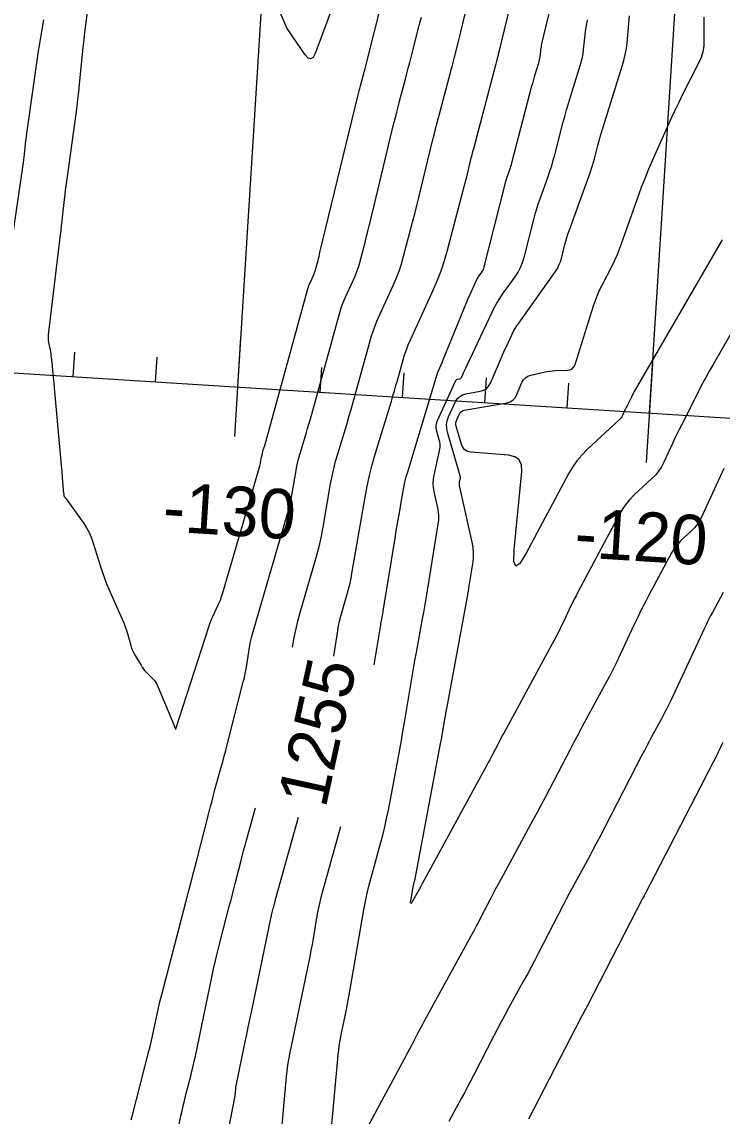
# Model space of a CAD drawing. Extents: x 658976 to 668726, y 639543 to 647196.
# Drawn here: x 661695.1 to 661779.9, y 641758.1 to 641890.7 of the extents above; entities that cross this region are included whole.
import ezdxf

# ---------------------------------------------------------------- set-up
doc = ezdxf.new("R2010")
doc.units = 0
for name, color, linetype in [('Ex_Contour Labels', 7, 'Continuous'), ('Ex_Major Contours', 7, 'Continuous'), ('Ex_Minor Contours', 7, 'Continuous'), ('R_Axis', 7, 'Continuous'), ('R_Axis Annot', 7, 'Continuous'), ('R_Grid', 7, 'Continuous')]:
    doc.layers.add(name, color=color, linetype=linetype)

msp = doc.modelspace()

# ---------------------------------------------------------------- linework, layer by layer
at = {"layer": 'Ex_Major Contours'}
for points in [[(661732.85, 641813.83), (661733.34, 641816.91), (661733.44, 641817.5), (661733.56, 641818.08), (661733.7, 641818.66), (661733.86, 641819.23), (661734.53, 641821.51), (661734.68, 641822.09), (661734.83, 641822.66), (661734.95, 641823.24), (661735.06, 641823.83), (661736.66, 641833.08), (661736.91, 641834.4), (661737.19, 641835.7), (661737.52, 641837), (661737.89, 641838.28), (661739.84, 641844.73), (661740.03, 641845.35), (661740.21, 641845.98), (661740.39, 641846.6), (661740.56, 641847.22), (661741.25, 641849.72), (661741.44, 641850.34), (661741.65, 641850.95), (661741.88, 641851.56), (661742.14, 641852.15), (661744.87, 641858.1), (661745.39, 641859.3), (661745.86, 641860.51), (661746.27, 641861.75), (661746.63, 641863), (661748.66, 641870.73), (661748.76, 641871.12), (661748.86, 641871.5), (661748.96, 641871.88), (661749.05, 641872.27), (661749.42, 641873.8), (661749.51, 641874.19), (661749.61, 641874.57), (661749.71, 641874.95), (661749.81, 641875.33), (661752.5, 641885.47), (661752.53, 641885.6), (661752.56, 641885.73), (661752.6, 641885.86), (661752.63, 641885.99), (661752.77, 641886.52), (661752.8, 641886.65), (661752.83, 641886.78), (661752.86, 641886.91), (661752.9, 641887.04), (661757.15, 641904.55)], [(661779.98, 641803.37), (661779.9, 641803.2), (661779.83, 641803.03), (661779.52, 641802.34), (661779.44, 641802.17), (661779.36, 641802), (661779.28, 641801.84), (661779.19, 641801.67), (661778.48, 641800.3), (661778.34, 641800.01), (661778.19, 641799.73), (661778.04, 641799.45), (661777.89, 641799.16), (661770.58, 641785.02), (661770.55, 641784.96), (661770.52, 641784.91), (661770.49, 641784.85), (661770.47, 641784.8), (661770.35, 641784.58), (661770.32, 641784.53), (661770.29, 641784.47), (661770.26, 641784.42), (661770.23, 641784.36), (661763.6, 641771.5), (661763.53, 641771.37), (661763.46, 641771.24), (661763.39, 641771.1), (661763.31, 641770.97), (661763.02, 641770.44), (661762.95, 641770.31), (661762.88, 641770.18), (661762.81, 641770.04), (661762.74, 641769.91), (661756.44, 641757.73)], [(661717.06, 641740.79), (661720.89, 641760.56), (661720.9, 641760.63), (661720.91, 641760.7), (661720.92, 641760.77), (661720.93, 641760.84), (661720.99, 641761.57), (661721, 641761.62), (661721.01, 641761.67), (661721.02, 641761.73), (661721.02, 641761.78), (661722.12, 641767.08), (661722.31, 641767.98), (661722.5, 641768.88), (661722.68, 641769.78), (661722.87, 641770.68), (661725.23, 641782.04), (661725.26, 641782.18), (661725.29, 641782.32), (661725.32, 641782.46), (661725.36, 641782.59), (661725.53, 641783.24), (661725.55, 641783.33), (661725.58, 641783.42), (661725.6, 641783.51), (661725.62, 641783.6), (661725.72, 641783.97), (661725.74, 641784.06), (661725.76, 641784.15), (661725.79, 641784.24), (661725.81, 641784.33), (661728.57, 641794.3)]]:
    msp.add_lwpolyline(points, dxfattribs=at)
at = {"layer": 'Ex_Minor Contours'}
for points in [[(661727.84, 641814.93), (661728.01, 641815.89), (661728.24, 641816.98), (661728.5, 641818.06), (661728.79, 641819.13), (661730.57, 641825.22), (661730.88, 641826.33), (661731.16, 641827.45), (661731.4, 641828.58), (661731.61, 641829.71), (661732.47, 641834.7), (661732.65, 641835.62), (661732.85, 641836.53), (661733.08, 641837.43), (661733.33, 641838.33), (661734.42, 641841.9), (661734.68, 641842.8), (661734.95, 641843.69), (661735.2, 641844.59), (661735.45, 641845.49), (661737.17, 641851.74), (661737.44, 641852.65), (661737.75, 641853.54), (661738.09, 641854.42), (661738.47, 641855.28), (661740.04, 641858.72), (661740.42, 641859.59), (661740.76, 641860.47), (661741.06, 641861.36), (661741.32, 641862.27), (661742.41, 641866.42), (661742.67, 641867.42), (661742.92, 641868.41), (661743.17, 641869.41), (661743.42, 641870.41), (661744.54, 641875.07), (661744.79, 641876.11), (661745.05, 641877.14), (661745.32, 641878.18), (661745.59, 641879.21), (661746.96, 641884.38), (661747.09, 641884.89), (661747.23, 641885.4), (661747.36, 641885.91), (661747.49, 641886.41), (661748.01, 641888.45), (661748.14, 641888.95), (661748.26, 641889.46), (661748.39, 641889.97), (661748.51, 641890.48), (661751.31, 641901.98)], [(661737.74, 641812.76), (661738.51, 641817.38), (661738.54, 641817.56), (661738.57, 641817.74), (661738.6, 641817.91), (661738.63, 641818.09), (661738.76, 641818.79), (661738.79, 641818.97), (661738.83, 641819.15), (661738.86, 641819.32), (661738.88, 641819.5), (661740.32, 641828.37), (661740.43, 641829.03), (661740.54, 641829.68), (661740.65, 641830.33), (661740.76, 641830.99), (661741.21, 641833.59), (661741.33, 641834.24), (661741.47, 641834.89), (661741.64, 641835.53), (661741.82, 641836.16), (661745.47, 641848.23), (661745.48, 641848.24), (661745.48, 641848.26), (661745.49, 641848.27), (661745.49, 641848.29), (661745.51, 641848.35), (661745.51, 641848.36), (661745.52, 641848.38), (661745.52, 641848.39), (661745.53, 641848.41), (661745.86, 641849.12), (661745.92, 641849.25), (661745.97, 641849.37), (661746.02, 641849.5), (661746.08, 641849.63), (661748.99, 641856.76), (661749.11, 641857.06), (661749.24, 641857.36), (661749.37, 641857.65), (661749.51, 641857.94), (661750.21, 641859.45), (661750.28, 641859.57), (661750.34, 641859.69), (661750.41, 641859.8), (661750.49, 641859.91), (661750.8, 641860.36), (661750.88, 641860.47), (661750.94, 641860.59), (661750.99, 641860.71), (661751.03, 641860.84), (661753.65, 641871.15), (661753.71, 641871.36), (661753.77, 641871.56), (661753.83, 641871.77), (661753.9, 641871.97), (661754.2, 641872.79), (661754.27, 641872.99), (661754.33, 641873.2), (661754.4, 641873.4), (661754.45, 641873.61), (661756.87, 641882.91), (661756.96, 641883.22), (661757.05, 641883.54), (661757.14, 641883.85), (661757.23, 641884.17), (661757.71, 641885.71), (661757.76, 641885.88), (661757.8, 641886.06), (661757.84, 641886.23), (661757.86, 641886.41), (661757.93, 641887.13), (661757.95, 641887.31), (661757.97, 641887.49), (661758.01, 641887.66), (661758.04, 641887.84), (661761.38, 641901.77)], [(661704.08, 641900.36), (661702.77, 641890.3), (661702.66, 641889.4), (661702.56, 641888.5), (661702.46, 641887.61), (661702.37, 641886.71), (661702.01, 641883.11), (661701.92, 641882.21), (661701.82, 641881.31), (661701.71, 641880.42), (661701.59, 641879.52), (661700.46, 641871.32), (661700.39, 641870.79), (661700.32, 641870.25), (661700.26, 641869.71), (661700.2, 641869.17), (661699.96, 641867.02), (661699.9, 641866.48), (661699.84, 641865.94), (661699.77, 641865.4), (661699.71, 641864.86), (661698.26, 641852.76), (661698.25, 641852.52), (661698.24, 641852.3), (661698.26, 641852.07), (661698.3, 641851.84), (661698.47, 641850.92), (661698.51, 641850.7), (661698.55, 641850.47), (661698.58, 641850.24), (661698.61, 641850.01), (661698.72, 641849.06), (661698.75, 641848.83), (661698.77, 641848.6), (661698.79, 641848.36), (661698.82, 641848.13), (661699.87, 641836.49), (661699.89, 641836.23), (661699.91, 641835.97), (661699.94, 641835.71), (661699.96, 641835.44), (661700.06, 641834.02), (661700.07, 641833.94), (661700.08, 641833.86), (661700.08, 641833.79), (661700.09, 641833.71), (661700.13, 641833.34), (661700.14, 641833.3), (661700.15, 641833.25), (661700.17, 641833.21), (661700.2, 641833.18), (661700.3, 641833.03), (661700.33, 641832.99), (661700.36, 641832.96), (661700.38, 641832.92), (661700.41, 641832.88), (661702.55, 641829.88), (661702.9, 641829.35), (661703.2, 641828.81), (661703.45, 641828.24), (661703.66, 641827.65), (661704.59, 641824.67), (661704.82, 641823.97), (661705.06, 641823.28), (661705.33, 641822.6), (661705.61, 641821.93), (661707.36, 641817.93), (661707.5, 641817.6), (661707.63, 641817.26), (661707.74, 641816.92), (661707.85, 641816.57), (661708.26, 641815.11), (661708.36, 641814.8), (661708.48, 641814.5), (661708.62, 641814.2), (661708.77, 641813.92), (661709.5, 641812.71), (661709.64, 641812.48), (661709.81, 641812.26), (661709.98, 641812.04), (661710.17, 641811.84), (661710.95, 641811.06), (661711.13, 641810.86), (661711.29, 641810.64), (661711.43, 641810.41), (661711.55, 641810.16), (661713.5, 641805.41), (661713.53, 641805.36), (661713.55, 641805.31), (661713.56, 641805.26), (661713.58, 641805.21), (661713.66, 641805), (661713.68, 641804.96), (661713.69, 641804.95), (661713.71, 641804.96), (661713.73, 641805), (661717.7, 641817.37), (661717.82, 641817.72), (661717.94, 641818.06), (661718.08, 641818.39), (661718.23, 641818.72), (661718.86, 641820.04), (661719.01, 641820.37), (661719.15, 641820.7), (661719.27, 641821.04), (661719.38, 641821.39), (661723.86, 641836.71), (661723.9, 641836.85), (661723.93, 641837), (661723.97, 641837.15), (661723.99, 641837.3), (661724.11, 641837.95), (661724.13, 641838.07), (661724.16, 641838.19), (661724.19, 641838.31), (661724.22, 641838.42), (661724.36, 641838.89), (661724.4, 641839.01), (661724.43, 641839.13), (661724.46, 641839.24), (661724.5, 641839.36), (661729.72, 641858.32), (661729.78, 641858.53), (661729.85, 641858.74), (661729.93, 641858.95), (661730.02, 641859.15), (661730.39, 641859.96), (661730.48, 641860.16), (661730.56, 641860.37), (661730.63, 641860.58), (661730.69, 641860.79), (661730.95, 641861.77), (661731.01, 641862), (661731.07, 641862.24), (661731.13, 641862.47), (661731.18, 641862.71), (661735.77, 641881.69), (661735.84, 641881.99), (661735.92, 641882.3), (661736, 641882.6), (661736.08, 641882.91), (661736.4, 641884.12), (661736.48, 641884.43), (661736.56, 641884.73), (661736.64, 641885.04), (661736.72, 641885.34), (661738.85, 641893.72)], [(661734.54, 641897.51), (661730.59, 641886.82), (661730.34, 641886.35), (661730.07, 641886.18), (661729.75, 641886.28), (661729.4, 641886.67), (661727.2, 641889.85), (661727.2, 641889.86), (661725.47, 641893.87)], [(661708.31, 641757.63), (661708.46, 641758.22), (661710.46, 641765.95), (661710.6, 641766.51), (661710.74, 641767.07), (661710.86, 641767.63), (661710.98, 641768.19), (661711.45, 641770.44), (661711.57, 641771), (661711.7, 641771.56), (661711.83, 641772.12), (661711.98, 641772.68), (661714.94, 641784.03), (661715.26, 641785.26), (661715.58, 641786.48), (661715.9, 641787.71), (661716.21, 641788.94), (661717.74, 641794.94), (661717.92, 641795.62), (661718.1, 641796.3), (661718.28, 641796.98), (661718.46, 641797.65), (661719.21, 641800.36), (661719.4, 641801.03), (661719.58, 641801.71), (661719.76, 641802.39), (661719.94, 641803.07), (661721.89, 641810.7), (661722.02, 641811.21), (661722.13, 641811.73), (661722.23, 641812.25), (661722.32, 641812.77), (661722.65, 641814.86), (661722.74, 641815.38), (661722.84, 641815.89), (661722.97, 641816.41), (661723.11, 641816.91), (661727.22, 641830.96), (661727.39, 641831.59), (661727.55, 641832.23), (661727.68, 641832.86), (661727.8, 641833.51), (661728.29, 641836.33), (661728.39, 641836.85), (661728.5, 641837.36), (661728.63, 641837.87), (661728.78, 641838.38), (661729.39, 641840.4), (661729.54, 641840.9), (661729.69, 641841.41), (661729.83, 641841.92), (661729.98, 641842.43), (661733.45, 641855.03), (661733.61, 641855.59), (661733.8, 641856.14), (661734.01, 641856.68), (661734.24, 641857.22), (661735.22, 641859.34), (661735.45, 641859.87), (661735.66, 641860.42), (661735.84, 641860.97), (661736, 641861.53), (661736.68, 641864.09), (661736.84, 641864.71), (661737, 641865.33), (661737.15, 641865.94), (661737.3, 641866.56), (661740.15, 641878.38), (661740.32, 641879.05), (661740.49, 641879.72), (661740.66, 641880.39), (661740.83, 641881.06), (661741.54, 641883.73), (661741.72, 641884.4), (661741.89, 641885.07), (661742.07, 641885.74), (661742.24, 641886.4), (661743.25, 641890.38), (661743.47, 641891.26)], [(661784.9, 641859.68), (661778.81, 641849.17), (661778.34, 641848.34), (661777.88, 641847.5), (661777.43, 641846.66), (661777, 641845.81), (661774.98, 641841.82), (661774.7, 641841.27), (661774.43, 641840.71), (661774.16, 641840.14), (661773.89, 641839.58), (661772.84, 641837.31), (661772.55, 641836.76), (661772.21, 641836.25), (661771.83, 641835.77), (661771.4, 641835.33), (661769.22, 641833.31), (661768.73, 641832.81), (661768.29, 641832.28), (661767.89, 641831.72), (661767.53, 641831.11), (661762.44, 641821.58), (661762.21, 641821.15), (661761.98, 641820.71), (661761.77, 641820.27), (661761.56, 641819.83), (661760.72, 641818.05), (661760.51, 641817.6), (661760.3, 641817.16), (661760.07, 641816.72), (661759.84, 641816.29), (661753.46, 641804.51), (661753.28, 641804.19), (661753.11, 641803.86), (661752.94, 641803.54), (661752.77, 641803.21), (661752.1, 641801.91), (661751.93, 641801.59), (661751.76, 641801.26), (661751.58, 641800.94), (661751.41, 641800.62), (661743.6, 641786.3), (661743.58, 641786.26), (661743.56, 641786.23), (661743.54, 641786.19), (661743.52, 641786.15), (661743.44, 641786), (661743.42, 641785.97), (661743.4, 641785.93), (661743.38, 641785.89), (661743.36, 641785.85), (661742.41, 641784.12), (661742.27, 641783.9), (661742.19, 641783.84), (661742.17, 641783.94), (661742.2, 641784.19), (661742.52, 641786.06), (661742.53, 641786.13), (661742.55, 641786.19), (661742.56, 641786.26), (661742.58, 641786.32), (661742.65, 641786.58), (661742.67, 641786.65), (661742.68, 641786.71), (661742.7, 641786.78), (661742.71, 641786.85), (661745.8, 641803.18), (661745.87, 641803.56), (661745.94, 641803.93), (661746.01, 641804.3), (661746.07, 641804.68), (661746.32, 641806.18), (661746.38, 641806.55), (661746.44, 641806.93), (661746.51, 641807.3), (661746.58, 641807.68), (661748.82, 641819.71), (661748.94, 641820.37), (661749.06, 641821.03), (661749.17, 641821.69), (661749.28, 641822.35), (661749.71, 641824.99), (661749.78, 641825.65), (661749.8, 641826.31), (661749.74, 641826.97), (661749.63, 641827.62), (661748.11, 641834.5), (661748.09, 641834.6), (661748.08, 641834.69), (661748.09, 641834.79), (661748.1, 641834.89), (661748.19, 641835.28), (661748.2, 641835.38), (661748.2, 641835.48), (661748.19, 641835.57), (661748.17, 641835.67), (661746.64, 641840.98), (661746.54, 641841.44), (661746.53, 641841.9), (661746.61, 641842.35), (661746.77, 641842.8), (661747.62, 641844.66), (661747.84, 641845.02), (661748.12, 641845.3), (661748.46, 641845.5), (661748.86, 641845.61), (661750.61, 641845.92), (661751.01, 641846.03), (661751.35, 641846.23), (661751.62, 641846.52), (661751.83, 641846.88), (661753.17, 641850), (661753.32, 641850.35), (661753.48, 641850.71), (661753.64, 641851.06), (661753.81, 641851.42), (661754.47, 641852.83), (661754.65, 641853.18), (661754.84, 641853.51), (661755.04, 641853.85), (661755.26, 641854.17), (661759.71, 641860.43), (661759.95, 641860.8), (661760.14, 641861.18), (661760.31, 641861.58), (661760.43, 641861.99), (661760.86, 641863.69), (661760.98, 641864.11), (661761.1, 641864.53), (661761.23, 641864.95), (661761.38, 641865.36), (661763.95, 641872.5), (661764.09, 641872.89), (661764.21, 641873.28), (661764.33, 641873.68), (661764.44, 641874.08), (661764.86, 641875.68), (661764.96, 641876.08), (661765.07, 641876.48), (661765.19, 641876.87), (661765.31, 641877.27), (661767.82, 641885.29), (661768.02, 641886), (661768.18, 641886.71), (661768.31, 641887.43), (661768.4, 641888.15), (661768.71, 641891.39)], [(661779.91, 641864.26), (661769.39, 641846.08), (661769.27, 641845.87), (661769.15, 641845.65), (661769.03, 641845.43), (661768.92, 641845.21), (661768.39, 641844.16), (661768.32, 641844.01), (661768.24, 641843.87), (661768.17, 641843.72), (661768.1, 641843.57), (661767.83, 641842.98), (661767.75, 641842.83), (661767.67, 641842.7), (661767.56, 641842.57), (661767.45, 641842.46), (661763.56, 641838.84), (661762.9, 641838.18), (661762.3, 641837.47), (661761.77, 641836.71), (661761.29, 641835.9), (661756.15, 641826.29), (661755.39, 641825.06), (661754.9, 641824.73), (661754.68, 641825.28), (661754.73, 641826.72), (661755.64, 641836.2), (661755.61, 641837), (661755.32, 641837.6), (661754.79, 641837.98), (661754.01, 641838.16), (661749.47, 641838.54), (661749.07, 641838.63), (661748.74, 641838.81), (661748.49, 641839.1), (661748.33, 641839.48), (661747.69, 641841.67), (661747.65, 641841.87), (661747.65, 641842.06), (661747.68, 641842.25), (661747.75, 641842.44), (661748.09, 641843.18), (661748.19, 641843.35), (661748.32, 641843.48), (661748.48, 641843.57), (661748.67, 641843.63), (661753.86, 641844.53), (661754.23, 641844.64), (661754.55, 641844.83), (661754.8, 641845.09), (661754.99, 641845.43), (661755.66, 641846.97), (661755.84, 641847.3), (661756.08, 641847.56), (661756.38, 641847.75), (661756.73, 641847.87), (661758.32, 641848.24), (661758.67, 641848.32), (661759.02, 641848.37), (661759.37, 641848.41), (661759.73, 641848.43), (661761.16, 641848.47), (661761.48, 641848.52), (661761.75, 641848.65), (661761.95, 641848.87), (661762.09, 641849.17), (661764.33, 641856.28), (661764.55, 641856.92), (661764.8, 641857.55), (661765.07, 641858.17), (661765.36, 641858.78), (661766.61, 641861.19), (661766.91, 641861.8), (661767.19, 641862.42), (661767.44, 641863.04), (661767.68, 641863.68), (661769.81, 641869.7), (661770.2, 641870.76), (661770.61, 641871.81), (661771.04, 641872.85), (661771.49, 641873.89), (661773.46, 641878.3), (661773.86, 641879.19), (661774.27, 641880.07), (661774.69, 641880.94), (661775.13, 641881.82), (661777.12, 641885.77), (661777.4, 641886.41), (661777.6, 641887.07), (661777.72, 641887.75), (661777.75, 641888.44), (661777.75, 641891.26)], [(661697.68, 641890.92), (661697.35, 641889.02), (661697.27, 641888.55), (661697.19, 641888.07), (661697.12, 641887.6), (661697.05, 641887.12), (661695.62, 641877.16), (661695.57, 641876.84), (661695.53, 641876.52), (661695.49, 641876.21), (661695.46, 641875.89), (661695.33, 641874.61), (661695.3, 641874.29), (661695.26, 641873.97), (661695.22, 641873.65), (661695.18, 641873.34), (661693.47, 641861.71)], [(661731.91, 641749.17), (661733.4, 641765.49), (661733.47, 641766.16), (661733.56, 641766.83), (661733.67, 641767.5), (661733.79, 641768.16), (661734.34, 641770.81), (661734.48, 641771.47), (661734.61, 641772.14), (661734.73, 641772.8), (661734.85, 641773.47), (661736.5, 641783.09), (661736.69, 641784.11), (661736.9, 641785.12), (661737.14, 641786.13), (661737.41, 641787.13), (661738.52, 641791.13), (661738.79, 641792.13), (661739.04, 641793.13), (661739.26, 641794.15), (661739.47, 641795.16), (661740.65, 641801.41), (661740.85, 641802.5), (661741.05, 641803.59), (661741.24, 641804.68), (661741.42, 641805.78), (661742.18, 641810.39), (661742.34, 641811.36), (661742.51, 641812.33), (661742.69, 641813.3), (661742.86, 641814.27), (661743.58, 641818.15), (661743.76, 641819.12), (661743.93, 641820.09), (661744.1, 641821.06), (661744.26, 641822.03), (661745.52, 641829.8), (661745.58, 641830.3), (661745.59, 641830.8), (661745.55, 641831.3), (661745.46, 641831.79), (661745.02, 641833.77), (661744.94, 641834.26), (661744.91, 641834.76), (661744.94, 641835.25), (661745.02, 641835.75), (661745.69, 641838.9), (661745.73, 641839.19), (661745.74, 641839.48), (661745.71, 641839.77), (661745.64, 641840.05), (661745.31, 641841.19), (661745.26, 641841.47), (661745.25, 641841.75), (661745.3, 641842.03), (661745.4, 641842.3), (661747.66, 641847.23), (661747.7, 641847.29), (661747.74, 641847.34), (661747.8, 641847.37), (661747.86, 641847.39), (661748.15, 641847.44), (661748.21, 641847.46), (661748.27, 641847.49), (661748.31, 641847.54), (661748.35, 641847.6), (661748.53, 641848.03), (661748.58, 641848.13), (661748.62, 641848.22), (661748.66, 641848.31), (661748.7, 641848.41), (661752.01, 641855.43), (661752.3, 641856.02), (661752.62, 641856.58), (661752.96, 641857.14), (661753.32, 641857.67), (661754.83, 641859.8), (661755.18, 641860.34), (661755.48, 641860.91), (661755.72, 641861.51), (661755.91, 641862.13), (661757.08, 641866.72), (661757.26, 641867.38), (661757.45, 641868.04), (661757.66, 641868.7), (661757.89, 641869.35), (661758.82, 641871.94), (661759.05, 641872.59), (661759.26, 641873.24), (661759.45, 641873.9), (661759.63, 641874.57), (661760.63, 641878.4), (661760.85, 641879.2), (661761.07, 641880), (661761.3, 641880.8), (661761.55, 641881.6), (661762.77, 641885.5), (661762.89, 641885.94), (661762.99, 641886.38), (661763.07, 641886.83), (661763.13, 641887.28), (661763.3, 641889.1), (661763.35, 641889.56), (661763.42, 641890.01), (661763.5, 641890.45), (661763.6, 641890.9)], [(661780.14, 641836.56), (661779.68, 641835.58), (661777.32, 641830.51), (661777.11, 641830.1), (661776.86, 641829.72), (661776.57, 641829.37), (661776.25, 641829.04), (661774.89, 641827.78), (661774.57, 641827.45), (661774.27, 641827.1), (661774.01, 641826.72), (661773.77, 641826.33), (661771.04, 641821.21), (661770.58, 641820.33), (661770.12, 641819.44), (661769.68, 641818.55), (661769.26, 641817.65), (661767.57, 641814.04), (661767.14, 641813.14), (661766.7, 641812.25), (661766.25, 641811.37), (661765.78, 641810.49), (661762.96, 641805.28), (661762.45, 641804.34), (661761.95, 641803.4), (661761.45, 641802.45), (661760.96, 641801.5), (661759, 641797.71), (661758.5, 641796.76), (661758, 641795.82), (661757.5, 641794.87), (661756.99, 641793.93), (661753.09, 641786.78), (661752.78, 641786.21), (661752.47, 641785.64), (661752.17, 641785.07), (661751.87, 641784.49), (661750.68, 641782.18), (661750.38, 641781.61), (661750.08, 641781.03), (661749.77, 641780.46), (661749.46, 641779.89), (661743.8, 641769.58), (661743.6, 641769.21), (661743.4, 641768.84), (661743.2, 641768.46), (661743, 641768.09), (661742.22, 641766.58), (661742.03, 641766.21), (661741.83, 641765.83), (661741.63, 641765.46), (661741.43, 641765.09), (661736.67, 641756.23)], [(661780.02, 641821.54), (661778.73, 641819.13), (661778.48, 641818.66), (661778.24, 641818.19), (661778.01, 641817.71), (661777.78, 641817.23), (661773.68, 641808.45), (661773.41, 641807.89), (661773.13, 641807.33), (661772.85, 641806.78), (661772.55, 641806.23), (661771.37, 641804.03), (661771.07, 641803.49), (661770.78, 641802.94), (661770.49, 641802.38), (661770.2, 641801.83), (661764.96, 641791.7), (661764.61, 641791.03), (661764.26, 641790.36), (661763.91, 641789.7), (661763.55, 641789.03), (661762.1, 641786.38), (661761.74, 641785.72), (661761.39, 641785.05), (661761.03, 641784.39), (661760.69, 641783.72), (661757.64, 641777.81), (661757.2, 641776.97), (661756.76, 641776.14), (661756.32, 641775.31), (661755.86, 641774.48), (661754.04, 641771.16), (661753.59, 641770.34), (661753.15, 641769.5), (661752.7, 641768.67), (661752.27, 641767.83), (661749.78, 641763.03), (661749.42, 641762.33), (661749.05, 641761.62), (661748.68, 641760.92), (661748.31, 641760.23), (661746.81, 641757.44)], [(661711.81, 641745.79), (661714.34, 641758.13), (661714.47, 641758.74), (661714.6, 641759.34), (661714.75, 641759.94), (661714.9, 641760.54), (661715.52, 641762.94), (661715.67, 641763.54), (661715.81, 641764.15), (661715.95, 641764.75), (661716.08, 641765.35), (661718.07, 641774.91), (661718.28, 641775.93), (661718.51, 641776.94), (661718.75, 641777.94), (661719.01, 641778.94), (661720.24, 641783.64), (661720.41, 641784.3), (661720.58, 641784.95), (661720.75, 641785.61), (661720.92, 641786.27), (661721.59, 641788.91), (661721.76, 641789.57), (661721.93, 641790.22), (661722.11, 641790.88), (661722.29, 641791.54), (661723.37, 641795.44)], [(661726.27, 641753.4), (661727.14, 641762.91), (661727.21, 641763.58), (661727.3, 641764.25), (661727.41, 641764.91), (661727.54, 641765.58), (661729.83, 641776.66), (661729.98, 641777.4), (661730.13, 641778.14), (661730.26, 641778.88), (661730.39, 641779.62), (661730.9, 641782.59), (661731.04, 641783.33), (661731.2, 641784.06), (661731.37, 641784.79), (661731.56, 641785.52), (661733.7, 641793.17)]]:
    msp.add_lwpolyline(points, dxfattribs=at)
at = {"layer": 'R_Axis'}
for p, q in [((661621.43, 641852.69), (663118.48, 641758.67)), ((661720.86, 641840.43), (661721.61, 641852.41)), ((661701.27, 641847.67), (661701.46, 641850.67)), ((661711.25, 641847.05), (661711.44, 641850.04)), ((661731.21, 641845.79), (661731.4, 641848.79)), ((661770.76, 641837.3), (661771.51, 641849.27)), ((661741.19, 641845.17), (661741.38, 641848.16)), ((661751.17, 641844.54), (661751.36, 641847.53)), ((661761.15, 641843.91), (661761.34, 641846.91))]:
    msp.add_line(p, q, dxfattribs=at)
at = {"layer": 'R_Grid'}
for p, q in [((661721.23, 641846.42), (661736.9, 642095.93)), ((661771.13, 641843.29), (661786.81, 642092.79)), ((661621.43, 641852.69), (663118.48, 641758.67))]:
    msp.add_line(p, q, dxfattribs=at)

# ---------------------------------------------------------------- texts
at = {"layer": 'Ex_Contour Labels'}
msp.add_text('1255', height=6, rotation=77.6463, dxfattribs=at).set_placement((661731.86, 641795.28))
at = {"layer": 'R_Axis Annot'}
for s, p in [('-130', (661712.02, 641828.96)), ('-120', (661761.92, 641825.83))]:
    msp.add_text(s, height=6, rotation=356.4063, dxfattribs=at).set_placement(p)

doc.saveas('drawing.dxf')
